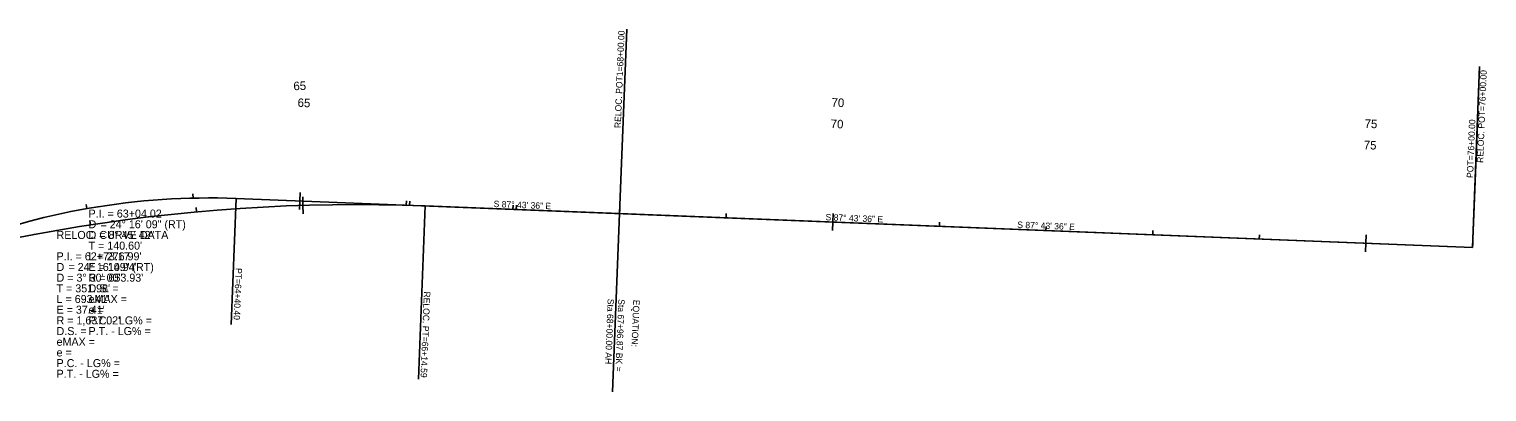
# Model space of a CAD drawing. Extents: x 1966701 to 1969292, y 1117367 to 1118089.
# Drawn here: x 1967926 to 1969292, y 1117750 to 1118089 of the extents above; entities that cross this region are included whole.
import ezdxf

# ---------------------------------------------------------------- set-up
doc = ezdxf.new("R2010")
doc.units = 0
for name, color, linetype in [('Level 1', 7, 'Continuous'), ('Level 19', 7, 'Continuous'), ('Level 2', 7, 'Continuous'), ('Level 3', 7, 'Continuous')]:
    doc.layers.add(name, color=color, linetype=linetype)

msp = doc.modelspace()

# ---------------------------------------------------------------- linework, layer by layer
at = {"layer": 'Level 1'}
for p, q in [((1969279, 1117884.9), (1969283.9, 1118009.1)), ((1968079.9, 1117931.3), (1968079.8, 1117935.3)), ((1968179.9, 1117928.6), (1968180.2, 1117936.6)), ((1967980.5, 1117921.5), (1967979.8, 1117925.4)), ((1968120.3, 1117930.9), (1968115.6, 1117812.9)), ((1968120.3, 1117930.9), (1969279, 1117884.9)), ((1968179.9, 1117928.6), (1968179.6, 1117920.6)), ((1968279.8, 1117924.6), (1968280, 1117928.6)), ((1968379.7, 1117920.6), (1968379.9, 1117924.6)), ((1968479.6, 1117916.7), (1968479.8, 1117920.7)), ((1968579.6, 1117912.7), (1968579.7, 1117916.7)), ((1968679.5, 1117908.7), (1968679.2, 1117900.8)), ((1968679.5, 1117908.7), (1968679.8, 1117916.7)), ((1968779.4, 1117904.8), (1968779.6, 1117908.8)), ((1968879.3, 1117900.8), (1968879.5, 1117904.8)), ((1968979.3, 1117896.8), (1968979.4, 1117900.8)), ((1969079.2, 1117892.9), (1969079.3, 1117896.9)), ((1969179.1, 1117888.9), (1969179.4, 1117896.9)), ((1969179.1, 1117888.9), (1969178.8, 1117880.9)), ((1969279, 1117884.9), (1969279.2, 1117888.9))]:
    msp.add_line(p, q, dxfattribs=at)
msp.add_arc((1968094.4, 1117277.5), 653.9, 87.7266, 111.9958, dxfattribs=at)
at = {"layer": 'Level 19'}
for p, q in [((1968083.1, 1117918.4), (1968082.8, 1117922.3)), ((1968182.9, 1117924.4), (1968182.7, 1117932.4)), ((1968182.9, 1117924.4), (1968183.2, 1117916.5)), ((1968282.9, 1117924.4), (1968283, 1117928.4)), ((1968297.5, 1117923.9), (1968479.6, 1117916.7)), ((1968382.8, 1117920.5), (1968383, 1117924.5)), ((1968479.6, 1117916.7), (1968479.8, 1117920.7)), ((1967983.9, 1117906.2), (1967983.3, 1117910.2)), ((1968479.6, 1117916.7), (1969279, 1117884.9)), ((1968579.6, 1117912.7), (1968579.7, 1117916.7)), ((1968679.5, 1117908.7), (1968679.2, 1117900.8)), ((1968679.5, 1117908.7), (1968679.8, 1117916.7)), ((1968779.4, 1117904.8), (1968779.6, 1117908.8)), ((1968879.3, 1117900.8), (1968879.5, 1117904.8)), ((1968979.3, 1117896.8), (1968979.4, 1117900.8)), ((1969079.2, 1117892.9), (1969079.3, 1117896.9)), ((1969179.1, 1117888.9), (1969179.4, 1117896.9)), ((1969179.1, 1117888.9), (1969178.8, 1117880.9))]:
    msp.add_line(p, q, dxfattribs=at)
msp.add_arc((1968232.6, 1116288.2), 1637, 87.7266, 111.9958, dxfattribs=at)
at = {"layer": 'Level 3'}
for p, q in [((1968479.6, 1117916.7), (1968486.5, 1118089.4)), ((1969279, 1117884.9), (1969285.7, 1118054.4)), ((1968297.5, 1117923.9), (1968291.1, 1117761.7)), ((1968479.6, 1117916.7), (1968473, 1117749.9))]:
    msp.add_line(p, q, dxfattribs=at)

# ---------------------------------------------------------------- texts
at = {"layer": 'Level 1'}
for s, rotation, p in [('POT=76+00.00', 87.7266, (1969279.6, 1117950)), ('PT=64+40.40', 267.7266, (1968119.8, 1117865.9))]:
    msp.add_text(s, height=6, rotation=rotation, dxfattribs=at).set_placement(p)
for s, p in [('P.I. = 63+04.02', (1967982, 1117913)), ('D', (1967982, 1117903)), ('    = 24%%d 16\' 09" (RT)', (1967982, 1117903)), ('D = 8%%d 45\' 42"', (1967982, 1117893)), ("T = 140.60'", (1967982, 1117883)), ("L = 276.99'", (1967982, 1117873)), ("E = 14.94'", (1967982, 1117863)), ("R = 653.93'", (1967982, 1117853)), ('eMAX = ', (1967982, 1117833)), ('D.S. = ', (1967982, 1117843)), ('e = ', (1967982, 1117823)), ('P.C. - LG% = ', (1967982, 1117813)), ('P.T. - LG% = ', (1967982, 1117803))]:
    msp.add_text(s, height=7.5, dxfattribs=at).set_placement(p)
at = {"layer": 'Level 19'}
for s, rotation, p in [('65', 1.7374, (1968174.1, 1118032.2)), ('70', 357.7266, (1968678.2, 1118016.9)), ('75', 357.7266, (1969177.8, 1117997.1))]:
    msp.add_text(s, height=8, rotation=rotation, dxfattribs=at).set_placement(p)
for s, p in [('RELOC. CURVE DATA', (1967952, 1117893)), ('P.I. = 62+73.17', (1967952, 1117873)), ('D', (1967952, 1117863)), ('    = 24%%d 16\' 09" (RT)', (1967952, 1117863)), ('D = 3%%d 30\' 00"', (1967952, 1117853)), ("T = 351.98'", (1967952, 1117843)), ("L = 693.41'", (1967952, 1117833)), ("E = 37.41'", (1967952, 1117823)), ("R = 1,637.02'", (1967952, 1117813)), ('D.S. = ', (1967952, 1117803)), ('eMAX = ', (1967952, 1117793)), ('e = ', (1967952, 1117783)), ('P.C. - LG% = ', (1967952, 1117773)), ('P.T. - LG% = ', (1967952, 1117763))]:
    msp.add_text(s, height=7.5, dxfattribs=at).set_placement(p)
at = {"layer": 'Level 2'}
for s, height, p in [('65', 8, (1968177.8, 1118016.7)), ('70', 8, (1968677.4, 1117996.9)), ('75', 8, (1969177, 1117977.1)), ('S 87%%d 43\' 36" E', 6, (1968672.6, 1117910.5))]:
    msp.add_text(s, height=height, rotation=357.7266, dxfattribs=at).set_placement(p)
at = {"layer": 'Level 3'}
for s, rotation, p in [('RELOC. POT1=68+00.00', 87.7266, (1968480.8, 1117996.7)), ('RELOC. POT=76+00.00', 87.7266, (1969289, 1117964.1)), ('S 87%%d 43\' 36" E', 357.7266, (1968361.5, 1117922.9)), ('S 87%%d 43\' 36" E', 357.7266, (1968852.3, 1117903.4)), ('RELOC. PT=66+14.59', 267.7266, (1968296.3, 1117843.9)), ('Sta 68+00.00 AH', 267.7266, (1968468.5, 1117837.1)), ('Sta 67+96.87 BK = ', 267.7266, (1968478.5, 1117836.7)), ('EQUATION:', 267.7266, (1968492.5, 1117836.1))]:
    msp.add_text(s, height=6, rotation=rotation, dxfattribs=at).set_placement(p)

doc.saveas('drawing.dxf')
